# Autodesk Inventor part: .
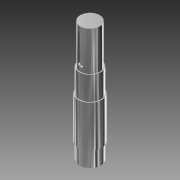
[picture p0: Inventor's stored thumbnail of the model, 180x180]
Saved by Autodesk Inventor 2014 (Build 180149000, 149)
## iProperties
Shininess: 20.0
Length Units: 11269
Angle Units: 11278
Time Units: 11290
Mass Units: 11283
Length Display Precision: 4
Angle Display Precision: 4
Created: 2001-03
Part Number: .
Material: Steel, Mild
Description: Output Shaft.
Document SubType Name: Modeling
Density: 7.86 g/cm^3
Appearance: Chrome - Polished
Density: 7.86
Volumn: 69.70827246452875
Area: 150.20802116696643
PropertySet Name: Model Information
Control State: 0
Master: False
Checked Out: False
ProtocolID: P00020918090103758
Protocol: P00020918090103758<@PID>[Version]<@EL>Version=2.0<@EL>[Synchronize]<@EL>ChangedVars=<@EL>[Calc]<@EL>CalcName=SHAFT3<@EL>Optim=1<@EL>WizardMode=2<@EL>[Main]<@EL>
Author: PaulN
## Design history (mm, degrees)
sketch "SketchBase" dims "d7" = 55 (= cone1_d1)
  geometry: L1 (0, 0)-(-8.127, 26.272); L2 (0, 0)-(-15.528, 22.697); L3 (0, 0)-(-23.14, 14.858); L4 (0, 0)-(-26.498, 7.356); L5 (0, 0)-(27.5, 0); L6 (0, 0)-(24.134, 13.184); L7 (0, 0)-(21.033, 17.716); L8 (0, 0)-(17.094, 21.541); 3 further points
  constraints: 16 end point, 1 coincident, 1 horizontal alignment, 1 vertical alignment, 12 other
  dimensions: "lw_l_nt_1" = 3 dimension on point (0, 0) L1.end point (0, 27.5); "lw_l_nt_2" = 6 dimension on point (0, 0) L2.end point (0, 27.5); "lw_r_nt_1" = 10 dimension on point (0, 0) L3.end point (0, 27.5); "lw_r_nt_2" = 13 dimension on point (0, 0) L4.end point (0, 27.5); "key_nt_1" = 0 dimension on point (0, 0) L5.end point (27.5, 0); "key_nt_2" = 5 dimension on point (0, 0) L6.end point (27.5, 0); "key_nt_3" = 7 dimension on point (0, 0) L7.end point (27.5, 0); "key_nt_4" = 9 dimension on point (0, 0) L8.end point (27.5, 0)
sketch "Sketch1"
  geometry: L1 (0, 0)-(27.5, 0); L2 (27.5, 0)-(27.5, 40); L3 (27.5, 40)-(0, 40); L4 (0, 40)-(0, 0)
  constraints: 8 end point, 1 horizontal, 1 parallel, 1 perpendicular, 1 other
  dimensions: "l_1" = 40 distance between parallel lines of L3 L1; "cone1_d1" = 55 diameter of L1.end L4; "cone2_d1" = 55 diameter of L2.end L4
revolve "element_1" sketch "Sketch1" stored, may be unused: angle "d3" = 90 deg
sketch "Sketch2"
  geometry: L1 (0, 40)-(0, 146); L2 (0, 146)-(30, 146); L3 (30, 146)-(30, 40); L4 (30, 40)-(0, 40); 1 further point
  constraints: 8 end point, 2 perpendicular, 1 point on line, 1 vertical
  dimensions: "cone1_d2" = 60 diameter of L3.end L1; "cone2_d2" = 60 diameter of L2.end L1; "l_2" = 106 distance between parallel lines of L4 L2; "dist2" = 40 distance from line of L4 point (0, 0)
revolve "element_2" sketch "Sketch2" stored, may be unused: angle "d10" = 90 deg
sketch "Sketch3"
  geometry: L1 (0, 146)-(0, 206); L2 (0, 206)-(27.5, 206); L3 (27.5, 206)-(27.5, 146); L4 (27.5, 146)-(0, 146); 1 further point
  constraints: 8 end point, 1 parallel, 1 perpendicular, 1 point on line, 1 vertical
  dimensions: "cone1_d3" = 55 diameter of L3.end L1; "cone2_d3" = 55 diameter of L2.end L1; "l_3" = 60 distance between parallel lines of L4 L2; "dist3" = 146 distance from line of L4 point (0, 0)
revolve "element_3" sketch "Sketch3" stored, may be unused: angle "d15" = 90 deg
sketch "Sketch4"
  geometry: L1 (0, 206)-(0, 306); L2 (0, 306)-(-25, 306); L3 (-25, 306)-(-25, 206); L4 (-25, 206)-(0, 206); 1 further point
  constraints: 8 end point, 1 parallel, 1 perpendicular, 1 point on line, 1 vertical
  dimensions: "cone1_d4" = 50 diameter of L3.end L1; "cone2_d4" = 50 diameter of L2.end L1; "l_4" = 100 distance between parallel lines of L4 L2; "dist4" = 206 distance from line of L4 point (0, 0)
revolve "element_4" sketch "Sketch4" stored, may be unused: angle "d28" = 90 deg
sketch "Sketch5"
  geometry: L1 (0, 40)-(0, 41); L2 (0, 41)-(-10, 41); L3 (-10, 41)-(-10, 40); L4 (-10, 40)-(0, 40); 1 further point
  constraints: 8 end point, 1 parallel, 1 perpendicular, 1 point on line, 1 vertical
  dimensions: "cone1_d5" = 20 diameter of L3.end L1; "cone2_d5" = 20 diameter of L2.end L1; "l_5" = 1 distance between parallel lines of L4 L2; "dist5" = 40 distance from line of point (0, 0) L4
revolve "element_5" sketch "Sketch5" stored, may be unused: angle "d33" = 90 deg
sketch "Sketch6"
  geometry: L1 (0, 50)-(0, 60); L2 (0, 60)-(-10, 60); L3 (-10, 60)-(-10, 50); L4 (-10, 50)-(0, 50); 1 further point
  constraints: 8 end point, 1 parallel, 1 perpendicular, 1 point on line, 1 vertical
  dimensions: "cone1_d6" = 20 diameter of L3.end L1; "cone2_d6" = 20 diameter of L2.end L1; "l_6" = 10 distance between parallel lines of L4 L2; "dist6" = 50 distance from line of L4 point (0, 0)
revolve "element_6" sketch "Sketch6" stored, may be unused: angle "d38" = 90 deg
sketch "Sketch7"
  geometry: L1 (0, 60)-(0, 70); L2 (0, 70)-(-10, 70); L3 (-10, 70)-(-10, 60); L4 (-10, 60)-(0, 60); 1 further point
  constraints: 8 end point, 1 parallel, 1 perpendicular, 1 point on line, 1 vertical
  dimensions: "cone1_d7" = 20 diameter of L3.end L1; "cone2_d7" = 20 diameter of L2.end L1; "l_7" = 10 distance between parallel lines of L4 L2; "dist7" = 60 distance from line of L4 point (0, 0)
revolve "element_7" sketch "Sketch7" stored, may be unused: angle "d43" = 90 deg
sketch "Sketch8"
  geometry: L1 (0, 70)-(0, 80); L2 (0, 80)-(-10, 80); L3 (-10, 80)-(-10, 70); L4 (-10, 70)-(0, 70); 1 further point
  constraints: 8 end point, 1 parallel, 1 perpendicular, 1 point on line, 1 vertical
  dimensions: "cone1_d8" = 20 diameter of L3.end L1; "cone2_d8" = 20 diameter of L2.end L1; "l_8" = 10 distance between parallel lines of L2 L4; "dist8" = 70 distance from line of point (0, 0) L4
revolve "element_8" sketch "Sketch8" stored, may be unused: angle "d48" = 90 deg
node "lockw Plane1"
node "lockw Plane2"
node "lockw Plane3"
node "lockw Plane4"
node "Key Plane1"
node "Key Plane12"
sketch "Sketch24"
  geometry: L1 (-7, 223)-(-7, 289); L2 (7, 289)-(7, 223); A1 r 7 centre (0, 289) between (7, 289) and (-7, 289); A2 r 7 centre (0, 223) between (-7, 223) and (7, 223); 2 further points
  constraints: 5 point on circle, 4 end point, 4 tangent, 2 centre point, 2 vertical alignment, 1 parallel, 1 vertical
  dimensions: "key_b_1" = 14 distance between parallel lines of L2 L1; "key_l_1" = 80 dimension on A2 A1; "key_dist_1" = 216 distance of point (0, 216) point (0, 0)
extrude "keyway_1" cut sketch "Sketch24" taper "d8" = 0 deg; distance "key_t_1" = 5.5
pattern_circular "Circular Pattern1" dims angle "d183" = 360 deg (computed from key_n_1)
node "Key Plane2"
node "Key Plane22"
node "Key Plane3"
node "Key Plane32"
sketch "Sketch29"
  geometry: L1 (-2.5, 35.5)-(-2.5, 45.5); L2 (2.5, 35.5)-(2.5, 45.5); A1 r 2.5 centre (0, 35.5) between (-2.5, 35.5) and (2.5, 35.5); A2 r 2.5 centre (0, 45.5) between (2.5, 45.5) and (-2.5, 45.5); 2 further points
  constraints: 5 point on circle, 4 end point, 4 tangent, 2 centre point, 2 vertical alignment, 1 parallel, 1 vertical
  dimensions: "key_b_3" = 5 distance between parallel lines of L1 L2; "key_dist_3" = 33 distance of point (0, 0) point (0, 33); "key_l_3" = 15 dimension on A2 A1
extrude "keyway_3" cut sketch "Sketch29" taper "d11" = 0 deg; distance "key_t_3" = 3
pattern_circular "Circular Pattern3" dims angle "d189" = 360 deg (computed from key_n_3)
node "Key Plane4"
workplane "Work Plane42"
body "Solid1"
other parameters: "key_radius_1" = 25, "key_radius_2" = 15, "key_radius_3" = 15, "key_radius_4" = 15
